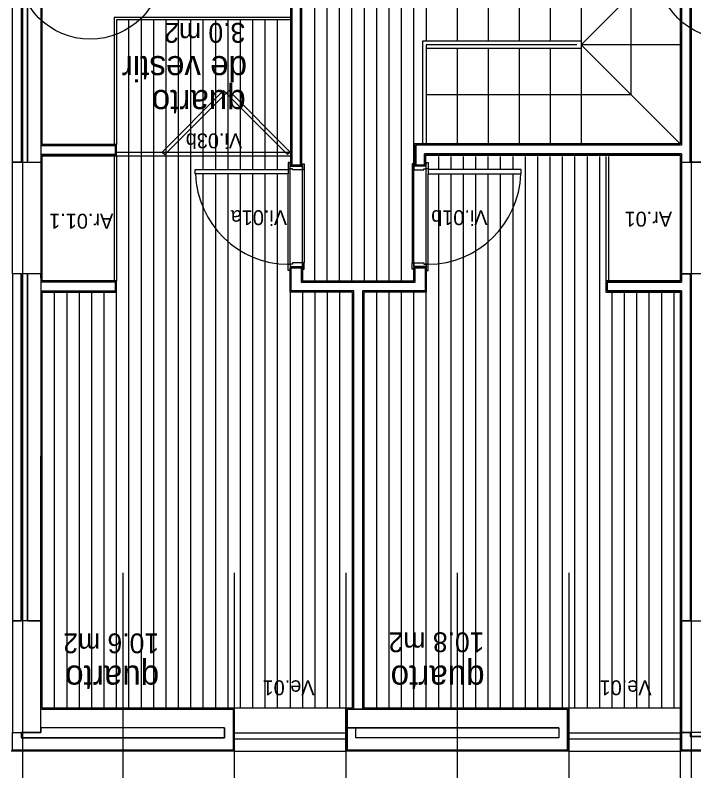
# Model space of a CAD drawing. Extents: x 1278 to 1356, y -253.7 to -224.
# Drawn here: x 1340.02 to 1345.5, y -247.08 to -240.98 of the extents above; entities that cross this region are included whole.
import ezdxf

# ---------------------------------------------------------------- set-up
doc = ezdxf.new("R2010")
doc.units = 0
for name, color, linetype in [('Level 1', 7, 'Continuous'), ('Level 10', 7, 'Continuous'), ('Level 13', 7, 'Continuous'), ('Level 2', 7, 'Continuous'), ('Level 25', 7, 'Continuous'), ('Level 4', 7, 'Continuous'), ('Level 40', 7, 'Continuous'), ('Level 60', 7, 'Continuous'), ('Level 65', 7, 'Continuous'), ('Level 66', 7, 'Continuous'), ('Level 67', 7, 'Continuous'), ('Level 69', 7, 'Continuous'), ('Level 70', 7, 'Continuous'), ('Level 93', 7, 'Continuous')]:
    doc.layers.add(name, color=color, linetype=linetype)

msp = doc.modelspace()

# ---------------------------------------------------------------- linework, layer by layer
at = {"layer": 'Level 1'}
for p, q in [((1340.2341, -246.584), (1340.234, -232.2657)), ((1340.0733, -236.7713), (1340.0733, -242.1713)), ((1340.124, -242.1713), (1340.124, -236.7713)), ((1345.474, -240.344), (1345.474, -242.1713)), ((1342.259, -240.414), (1342.259, -242.194)), ((1342.329, -242.194), (1342.329, -240.414)), ((1345.404, -240.414), (1345.404, -242.034)), ((1340.834, -242.109), (1340.834, -242.039)), ((1345.404, -242.034), (1343.259, -242.034)), ((1343.259, -242.034), (1343.259, -242.194)), ((1343.329, -242.194), (1343.329, -242.104)), ((1345.404, -242.104), (1343.329, -242.104)), ((1345.404, -242.104), (1345.404, -243.139)), ((1342.244, -242.194), (1342.344, -242.194)), ((1343.339, -242.194), (1343.2495, -242.194)), ((1342.244, -243.219), (1342.244, -243.024)), ((1342.244, -243.024), (1342.344, -243.024)), ((1342.254, -243.209), (1342.254, -243.024)), ((1342.334, -243.024), (1342.334, -243.139)), ((1343.344, -243.024), (1343.244, -243.024)), ((1343.254, -243.139), (1343.254, -243.024)), ((1343.334, -243.024), (1343.334, -243.209)), ((1340.0733, -243.0713), (1340.0733, -245.8713)), ((1340.124, -245.8713), (1340.124, -243.0713)), ((1345.474, -243.0713), (1345.474, -245.8713)), ((1340.834, -243.139), (1340.234, -243.139)), ((1340.834, -243.209), (1340.834, -243.139)), ((1342.334, -243.139), (1343.254, -243.139)), ((1344.804, -243.139), (1344.804, -243.209)), ((1345.404, -243.139), (1344.804, -243.139)), ((1340.234, -243.209), (1340.834, -243.209)), ((1342.759, -243.209), (1342.254, -243.209)), ((1342.759, -246.584), (1342.759, -243.209)), ((1342.829, -243.209), (1342.829, -246.584)), ((1343.334, -243.209), (1342.829, -243.209)), ((1344.804, -243.209), (1345.404, -243.209)), ((1345.404, -243.209), (1345.404, -246.914)), ((1340.2333, -246.584), (1341.784, -246.584)), ((1341.784, -246.584), (1341.784, -246.914)), ((1342.704, -246.914), (1342.704, -246.584)), ((1342.704, -246.584), (1344.484, -246.584)), ((1344.484, -246.584), (1344.484, -246.914)), ((1341.714, -246.734), (1341.714, -246.814)), ((1342.774, -246.814), (1342.774, -246.734)), ((1344.414, -246.734), (1344.414, -246.814)), ((1340.0733, -246.7713), (1340.0733, -246.814)), ((1345.474, -246.7713), (1345.474, -246.804)), ((1347.114, -246.804), (1345.474, -246.804)), ((1341.784, -246.914), (1340.0033, -246.914)), ((1344.484, -246.914), (1342.704, -246.914)), ((1347.184, -246.914), (1345.404, -246.914))]:
    msp.add_line(p, q, dxfattribs=at)
at = {"layer": 'Level 10'}
for p, q in [((1342.444, -243.129), (1342.444, -240.439)), ((1342.544, -243.129), (1342.544, -240.424)), ((1342.644, -243.129), (1342.644, -240.424)), ((1342.744, -243.129), (1342.744, -240.424)), ((1342.844, -243.129), (1342.844, -240.424)), ((1342.944, -243.129), (1342.944, -240.424)), ((1343.044, -243.129), (1343.044, -240.424)), ((1343.144, -243.129), (1343.144, -240.439)), ((1343.244, -242.194), (1343.244, -240.424)), ((1340.944, -246.574), (1340.944, -241.024)), ((1341.044, -246.574), (1341.044, -241.024)), ((1341.144, -246.574), (1341.144, -241.024)), ((1341.244, -246.574), (1341.244, -241.024)), ((1341.344, -246.574), (1341.344, -241.024)), ((1341.444, -246.574), (1341.444, -241.024)), ((1341.544, -242.229), (1341.544, -241.024)), ((1341.644, -242.229), (1341.644, -241.024)), ((1341.744, -242.229), (1341.744, -241.024)), ((1341.844, -242.229), (1341.844, -241.024)), ((1341.944, -242.229), (1341.944, -241.024)), ((1342.044, -242.229), (1342.044, -241.024)), ((1342.144, -242.229), (1342.144, -241.024)), ((1343.444, -242.229), (1343.444, -242.124)), ((1343.544, -242.229), (1343.544, -242.124)), ((1343.644, -242.229), (1343.644, -242.124)), ((1343.744, -242.229), (1343.744, -242.124)), ((1343.844, -242.229), (1343.844, -242.124)), ((1343.944, -242.229), (1343.944, -242.124)), ((1344.044, -242.229), (1344.044, -242.124)), ((1344.144, -246.574), (1344.144, -242.124)), ((1344.244, -246.574), (1344.244, -242.124)), ((1344.344, -246.574), (1344.344, -242.124)), ((1344.444, -246.574), (1344.444, -242.124)), ((1344.544, -246.574), (1344.544, -242.124)), ((1344.644, -246.574), (1344.644, -242.124)), ((1344.744, -246.574), (1344.744, -242.124)), ((1342.244, -242.994), (1342.244, -242.224)), ((1342.344, -242.984), (1342.344, -242.234)), ((1343.244, -242.984), (1343.244, -242.234)), ((1343.344, -242.994), (1343.344, -242.224)), ((1341.544, -246.574), (1341.544, -242.264)), ((1341.644, -246.574), (1341.644, -242.264)), ((1341.744, -246.574), (1341.744, -242.264)), ((1341.844, -246.574), (1341.844, -242.264)), ((1341.944, -246.574), (1341.944, -242.264)), ((1342.044, -246.574), (1342.044, -242.264)), ((1342.144, -246.574), (1342.144, -242.264)), ((1343.444, -246.574), (1343.444, -242.264)), ((1343.544, -246.574), (1343.544, -242.264)), ((1343.644, -246.574), (1343.644, -242.264)), ((1343.744, -246.574), (1343.744, -242.264)), ((1343.844, -246.574), (1343.844, -242.264)), ((1343.944, -246.574), (1343.944, -242.264)), ((1344.044, -246.574), (1344.044, -242.264)), ((1340.344, -246.574), (1340.344, -243.219)), ((1340.444, -246.574), (1340.444, -243.219)), ((1340.544, -246.574), (1340.544, -243.219)), ((1340.644, -246.574), (1340.644, -243.219)), ((1340.744, -246.574), (1340.744, -243.219)), ((1340.844, -246.574), (1340.844, -243.219)), ((1342.244, -243.219), (1342.244, -246.574)), ((1342.344, -243.219), (1342.344, -246.574)), ((1342.444, -243.219), (1342.444, -246.574)), ((1342.544, -243.219), (1342.544, -246.574)), ((1342.644, -243.219), (1342.644, -246.574)), ((1342.944, -246.574), (1342.944, -243.219)), ((1343.044, -246.574), (1343.044, -243.219)), ((1343.144, -246.574), (1343.144, -243.219)), ((1343.244, -246.574), (1343.244, -243.219)), ((1343.344, -246.574), (1343.344, -243.219)), ((1344.844, -246.574), (1344.844, -243.219)), ((1344.944, -246.574), (1344.944, -243.219)), ((1345.044, -246.574), (1345.044, -243.219)), ((1345.144, -246.574), (1345.144, -243.219)), ((1345.244, -246.574), (1345.244, -243.219)), ((1345.344, -246.574), (1345.344, -243.219))]:
    msp.add_line(p, q, dxfattribs=at)
at = {"layer": 'Level 13'}
for p, q in [((1342.244, -241.004), (1340.824, -241.004)), ((1340.824, -241.004), (1340.824, -242.029)), ((1342.244, -241.024), (1340.844, -241.024)), ((1340.844, -241.024), (1340.844, -242.029)), ((1341.2117, -242.089), (1341.7066, -241.594)), ((1341.2329, -242.1102), (1341.7279, -241.6152)), ((1341.7066, -241.594), (1341.7279, -241.6152)), ((1341.7491, -241.594), (1341.7279, -241.6152)), ((1342.2228, -242.1102), (1341.7279, -241.6152)), ((1342.244, -242.089), (1341.7491, -241.594)), ((1341.2117, -242.089), (1341.2329, -242.1102)), ((1342.244, -242.089), (1342.2228, -242.1102)), ((1340.824, -242.119), (1340.824, -243.129)), ((1340.844, -242.119), (1340.844, -243.129)), ((1342.229, -242.174), (1342.229, -242.224)), ((1342.239, -242.174), (1342.229, -242.174)), ((1342.239, -242.179), (1342.239, -242.174)), ((1343.349, -242.179), (1343.349, -242.174)), ((1343.349, -242.174), (1343.359, -242.174)), ((1343.359, -242.174), (1343.359, -242.224)), ((1344.794, -242.124), (1344.794, -243.129)), ((1344.814, -242.124), (1344.814, -243.129)), ((1341.479, -242.229), (1342.229, -242.229)), ((1341.479, -242.264), (1341.479, -242.229)), ((1342.229, -242.224), (1342.244, -242.224)), ((1342.229, -242.229), (1342.229, -242.264)), ((1342.244, -242.179), (1342.239, -242.179)), ((1342.244, -242.224), (1342.244, -242.179)), ((1342.244, -242.204), (1342.344, -242.204)), ((1342.244, -242.224), (1342.244, -242.204)), ((1342.264, -242.224), (1342.244, -242.224)), ((1342.264, -242.234), (1342.264, -242.224)), ((1342.344, -242.234), (1342.264, -242.234)), ((1342.344, -242.234), (1342.344, -242.189)), ((1342.344, -242.189), (1342.349, -242.189)), ((1342.344, -242.204), (1342.344, -242.234)), ((1342.359, -242.234), (1342.344, -242.234)), ((1342.349, -242.189), (1342.349, -242.184)), ((1342.349, -242.184), (1342.359, -242.184)), ((1342.359, -242.184), (1342.359, -242.234)), ((1343.229, -242.184), (1343.229, -242.234)), ((1343.239, -242.184), (1343.229, -242.184)), ((1343.229, -242.234), (1343.244, -242.234)), ((1343.239, -242.189), (1343.239, -242.184)), ((1343.244, -242.189), (1343.239, -242.189)), ((1343.244, -242.234), (1343.244, -242.189)), ((1343.344, -242.204), (1343.244, -242.204)), ((1343.244, -242.204), (1343.244, -242.234)), ((1343.244, -242.234), (1343.324, -242.234)), ((1343.324, -242.234), (1343.324, -242.224)), ((1343.324, -242.224), (1343.344, -242.224)), ((1343.344, -242.224), (1343.344, -242.179)), ((1343.344, -242.179), (1343.349, -242.179)), ((1343.344, -242.224), (1343.344, -242.204)), ((1343.359, -242.224), (1343.344, -242.224)), ((1344.109, -242.229), (1343.359, -242.229)), ((1343.359, -242.229), (1343.359, -242.264)), ((1344.109, -242.264), (1344.109, -242.229)), ((1342.229, -242.264), (1341.479, -242.264)), ((1343.359, -242.264), (1344.109, -242.264)), ((1342.229, -243.044), (1342.229, -242.994)), ((1342.229, -242.994), (1342.244, -242.994)), ((1342.244, -242.994), (1342.244, -243.039)), ((1342.264, -242.994), (1342.244, -242.994)), ((1342.244, -242.994), (1342.244, -243.014)), ((1342.244, -243.014), (1342.344, -243.014)), ((1342.344, -242.984), (1342.264, -242.984)), ((1342.264, -242.984), (1342.264, -242.994)), ((1342.344, -243.014), (1342.344, -242.984)), ((1342.359, -242.984), (1342.344, -242.984)), ((1342.344, -242.984), (1342.344, -243.029)), ((1342.344, -243.029), (1342.349, -243.029)), ((1342.349, -243.029), (1342.349, -243.034)), ((1342.359, -243.034), (1342.359, -242.984)), ((1343.229, -243.034), (1343.229, -242.984)), ((1343.229, -242.984), (1343.244, -242.984)), ((1343.244, -243.029), (1343.239, -243.029)), ((1343.239, -243.029), (1343.239, -243.034)), ((1343.244, -242.984), (1343.244, -243.029)), ((1343.244, -243.014), (1343.244, -242.984)), ((1343.244, -242.984), (1343.324, -242.984)), ((1343.344, -243.014), (1343.244, -243.014)), ((1343.324, -242.984), (1343.324, -242.994)), ((1343.324, -242.994), (1343.344, -242.994)), ((1343.344, -242.994), (1343.344, -243.014)), ((1343.359, -242.994), (1343.344, -242.994)), ((1343.344, -242.994), (1343.344, -243.039)), ((1343.359, -243.044), (1343.359, -242.994)), ((1342.239, -243.044), (1342.229, -243.044)), ((1342.244, -243.039), (1342.239, -243.039)), ((1342.239, -243.039), (1342.239, -243.044)), ((1342.349, -243.034), (1342.359, -243.034)), ((1343.239, -243.034), (1343.229, -243.034)), ((1343.344, -243.039), (1343.349, -243.039)), ((1343.349, -243.039), (1343.349, -243.044)), ((1343.349, -243.044), (1343.359, -243.044))]:
    msp.add_line(p, q, dxfattribs=at)
at = {"layer": 'Level 2'}
for p, q in [((1343.3433, -240.424), (1343.3433, -241.194)), ((1343.5933, -240.424), (1343.5933, -241.194)), ((1343.8433, -240.424), (1343.8433, -241.194)), ((1344.0933, -240.424), (1344.0933, -241.194)), ((1344.3433, -240.424), (1344.3433, -241.194)), ((1344.5933, -240.424), (1344.5933, -241.194)), ((1344.594, -240.424), (1344.594, -241.194)), ((1344.594, -241.224), (1345.394, -240.424)), ((1344.994, -240.824), (1344.994, -241.624)), ((1344.594, -241.194), (1343.3133, -241.194)), ((1343.3133, -241.194), (1343.3133, -242.024)), ((1344.594, -241.194), (1344.594, -241.254)), ((1343.3433, -241.224), (1343.3433, -242.024)), ((1343.344, -241.224), (1343.344, -242.024)), ((1344.5594, -241.224), (1343.344, -241.224)), ((1344.594, -241.254), (1343.344, -241.254)), ((1343.594, -241.254), (1343.594, -242.024)), ((1343.844, -241.254), (1343.844, -242.024)), ((1344.094, -241.254), (1344.094, -242.024)), ((1344.344, -241.254), (1344.344, -242.024)), ((1345.394, -241.224), (1344.594, -241.224)), ((1344.594, -241.224), (1345.394, -242.024)), ((1344.594, -241.254), (1344.594, -242.024)), ((1343.344, -241.624), (1344.994, -241.624)), ((1341.794, -246.574), (1342.694, -246.574)), ((1344.494, -246.574), (1345.394, -246.574)), ((1341.794, -246.774), (1342.694, -246.774)), ((1344.494, -246.774), (1345.394, -246.774)), ((1341.794, -246.824), (1342.694, -246.824)), ((1344.494, -246.824), (1345.394, -246.824)), ((1341.794, -246.924), (1342.694, -246.924)), ((1344.494, -246.924), (1345.394, -246.924))]:
    msp.add_line(p, q, dxfattribs=at)
at = {"layer": 'Level 25'}
msp.add_lwpolyline([(1345.6333, -246.7713), (1345.4033, -246.7713), (1345.4033, -245.8713), (1345.6333, -245.8713)], close=True, dxfattribs=at)
at = {"layer": 'Level 4'}
for p, q in [((1340.844, -242.089), (1342.244, -242.089)), ((1340.844, -242.119), (1342.244, -242.119)), ((1342.359, -242.234), (1342.359, -242.984)), ((1343.229, -242.234), (1343.229, -242.984)), ((1342.229, -242.994), (1342.229, -242.264)), ((1343.359, -242.994), (1343.359, -242.264))]:
    msp.add_line(p, q, dxfattribs=at)
for centre, start_param, end_param in [((1342.229, -242.2308), 1.614288, 3.141593), ((1343.359, -242.2308), 3.141593, 4.668897)]:
    msp.add_ellipse(centre, major_axis=(0, 0.7632), ratio=0.982661, start_param=start_param, end_param=end_param, dxfattribs=at)
at = {"layer": 'Level 65'}
for p, q in [((1342.249, -240.424), (1342.249, -242.194)), ((1342.339, -242.194), (1342.339, -240.424)), ((1345.394, -240.424), (1345.394, -242.024)), ((1340.244, -242.029), (1340.244, -240.684)), ((1340.844, -242.029), (1340.244, -242.029)), ((1340.844, -242.119), (1340.844, -242.029)), ((1343.249, -242.024), (1343.249, -242.194)), ((1345.394, -242.024), (1343.249, -242.024)), ((1343.339, -242.194), (1343.339, -242.114)), ((1343.339, -242.114), (1345.394, -242.114)), ((1345.394, -242.114), (1345.394, -243.129)), ((1340.244, -242.119), (1340.844, -242.119)), ((1340.244, -243.129), (1340.244, -242.119)), ((1342.344, -243.024), (1342.344, -243.129)), ((1343.244, -243.129), (1343.244, -243.024)), ((1343.344, -243.024), (1343.344, -243.219)), ((1340.844, -243.129), (1340.244, -243.129)), ((1340.844, -243.219), (1340.844, -243.129)), ((1342.344, -243.129), (1343.244, -243.129)), ((1344.794, -243.129), (1344.794, -243.219)), ((1345.394, -243.129), (1344.794, -243.129)), ((1340.244, -246.574), (1340.244, -243.219)), ((1340.244, -243.219), (1340.844, -243.219)), ((1342.749, -243.219), (1342.244, -243.219)), ((1342.749, -246.574), (1342.749, -243.219)), ((1343.344, -243.219), (1342.839, -243.219)), ((1342.839, -243.219), (1342.839, -246.574)), ((1344.794, -243.219), (1345.394, -243.219)), ((1345.394, -243.219), (1345.394, -246.924)), ((1340.244, -246.574), (1341.794, -246.574)), ((1341.794, -246.574), (1341.794, -246.924)), ((1342.694, -246.924), (1342.694, -246.574)), ((1342.694, -246.574), (1342.749, -246.574)), ((1342.839, -246.574), (1344.494, -246.574)), ((1344.494, -246.574), (1344.494, -246.924)), ((1341.794, -246.924), (1339.9933, -246.924)), ((1344.494, -246.924), (1342.694, -246.924)), ((1347.194, -246.924), (1345.394, -246.924))]:
    msp.add_line(p, q, dxfattribs=at)
at = {"layer": 'Level 66'}
for p, q in [((1340.834, -242.039), (1340.234, -242.039)), ((1340.834, -242.109), (1340.234, -242.109)), ((1345.564, -242.1713), (1345.474, -242.1713)), ((1341.714, -246.734), (1340.2333, -246.734)), ((1340.2333, -246.734), (1340.2333, -246.7713)), ((1344.414, -246.734), (1342.774, -246.734)), ((1340.2333, -246.7713), (1340.0733, -246.7713)), ((1345.6333, -246.7713), (1345.474, -246.7713)), ((1341.714, -246.814), (1340.0733, -246.814)), ((1344.414, -246.814), (1342.774, -246.814))]:
    msp.add_line(p, q, dxfattribs=at)
for points in [[(1340.2333, -243.0713), (1340.0033, -243.0713), (1340.0033, -242.1713), (1340.2333, -242.1713)], [(1345.404, -242.1713), (1345.634, -242.1713), (1345.634, -243.0713), (1345.404, -243.0713)], [(1340.2333, -245.8713), (1340.0033, -245.8713), (1340.0033, -246.7713), (1340.2333, -246.7713)], [(1345.6333, -246.7713), (1345.4033, -246.7713), (1345.4033, -245.8713), (1345.6333, -245.8713)]]:
    msp.add_lwpolyline(points, close=True, dxfattribs=at)
at = {"layer": 'Level 67'}
for points in [[(1340.0733, -242.1713), (1340.0033, -242.1713), (1340.0033, -236.7713), (1340.0733, -236.7713)], [(1340.2333, -242.1713), (1340.234, -242.1713), (1340.234, -242.109), (1340.834, -242.109), (1340.834, -242.039), (1340.234, -242.039), (1340.2333, -236.7713), (1340.124, -236.7713), (1340.124, -242.1713), (1340.234, -242.1713)], [(1345.474, -242.1713), (1345.474, -240.344), (1343.274, -240.344), (1343.274, -239.444), (1342.274, -239.444), (1342.274, -238.544), (1340.234, -238.544), (1340.234, -238.614), (1342.204, -238.614), (1342.204, -239.514), (1343.204, -239.514), (1343.204, -240.334), (1343.169, -240.334), (1343.169, -240.414), (1345.404, -240.414), (1345.404, -242.034), (1343.259, -242.034), (1343.259, -242.194), (1343.329, -242.194), (1343.329, -242.104), (1345.404, -242.104), (1345.404, -242.1713), (1345.474, -242.1713), (1345.474, -240.344)], [(1342.329, -240.414), (1342.329, -242.194), (1342.259, -242.194), (1342.259, -240.414)], [(1342.829, -246.584), (1342.759, -246.584), (1342.759, -243.209), (1342.254, -243.209), (1342.254, -243.024), (1342.334, -243.024), (1342.334, -243.139), (1343.254, -243.139), (1343.254, -243.024), (1343.334, -243.024), (1343.334, -243.209), (1342.829, -243.209)], [(1340.0733, -243.0713), (1340.0033, -243.0713), (1340.0033, -245.8713), (1340.0733, -245.8713)], [(1340.124, -243.0713), (1340.124, -245.8713), (1340.2333, -245.8713), (1340.234, -243.209), (1340.834, -243.209), (1340.834, -243.139), (1340.234, -243.139), (1340.2333, -243.0713)], [(1345.474, -245.8713), (1345.4033, -245.8713), (1345.404, -243.209), (1344.804, -243.209), (1344.804, -243.139), (1345.404, -243.139), (1345.404, -243.0713), (1345.474, -243.0713), (1345.474, -245.8713)], [(1341.784, -246.584), (1341.784, -246.914), (1340.0033, -246.914), (1340.0033, -246.7713), (1340.0733, -246.7713), (1340.0733, -246.814), (1341.714, -246.814), (1341.714, -246.734), (1340.2333, -246.734), (1340.2333, -246.584)], [(1342.774, -246.734), (1344.414, -246.734), (1344.414, -246.814), (1342.774, -246.814), (1342.774, -246.734), (1342.704, -246.734), (1342.704, -246.914), (1344.484, -246.914), (1344.484, -246.584), (1342.704, -246.584), (1342.704, -246.734)], [(1347.184, -246.584), (1347.184, -246.914), (1345.404, -246.914), (1345.4033, -246.7713), (1345.474, -246.7713), (1345.474, -246.804), (1347.114, -246.804), (1347.114, -246.734), (1345.6333, -246.734), (1345.6333, -246.584)]]:
    msp.add_lwpolyline(points, close=True, dxfattribs=at)
at = {"layer": 'Level 69'}
for centre in [(1340.6308, -240.5951), (1345.7869, -240.5951)]:
    msp.add_circle(centre, 0.5842, dxfattribs=at)
at = {"layer": 'Level 70'}
for p, q in [((1340.084, -229.6198), (1340.084, -250.7923)), ((1345.484, -250.7923), (1345.484, -229.6198))]:
    msp.add_line(p, q, dxfattribs=at)
at = {"layer": 'Level 93'}
for p, q in [((1340.894, -245.4838), (1340.894, -250.4459)), ((1341.794, -245.4838), (1341.794, -250.4459)), ((1342.694, -245.4838), (1342.694, -250.4459)), ((1343.594, -245.4838), (1343.594, -250.4459)), ((1344.494, -245.4838), (1344.494, -250.4459)), ((1345.394, -245.4838), (1345.394, -250.4459))]:
    msp.add_line(p, q, dxfattribs=at)

# ---------------------------------------------------------------- texts
at = {"layer": 'Level 40'}
for s, rotation, p in [('Vi.03b', 180.00001, (1341.8576, -241.939)), ('Ar.01.1', 179.99999, (1340.8175, -242.5872)), ('Vi.01a', 180.00001, (1342.2203, -242.5589)), ('Vi.01b', 180.00001, (1343.8385, -242.5589)), ('Ar.01', 179.99999, (1345.328, -242.5706)), ('Ve.01', 180.00001, (1342.442, -246.3511)), ('Ve.01', 180.00001, (1345.1623, -246.3511))]:
    msp.add_text(s, height=0.12, rotation=rotation, dxfattribs=at).set_placement(p)
at = {"layer": 'Level 60'}
for s, height, p in [('3.0 m2', 0.16, (1341.8827, -241.0475)), ('de vestir', 0.2, (1341.8969, -241.3153)), ('de vestir', 0.2, (1341.8969, -241.3153)), ('quarto', 0.2, (1341.886, -241.5889)), ('10.6 m2', 0.16, (1341.1874, -245.9726)), ('10.8 m2', 0.16, (1343.8132, -245.9642)), ('quarto', 0.2, (1341.1874, -246.232)), ('quarto', 0.2, (1343.8145, -246.232))]:
    msp.add_text(s, height=height, rotation=180, dxfattribs=at).set_placement(p)

doc.saveas('drawing.dxf')
